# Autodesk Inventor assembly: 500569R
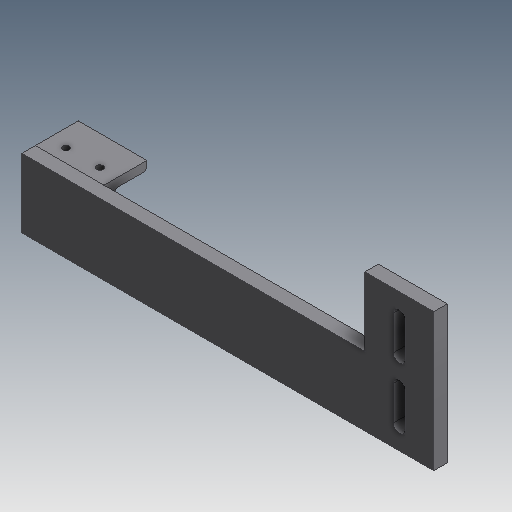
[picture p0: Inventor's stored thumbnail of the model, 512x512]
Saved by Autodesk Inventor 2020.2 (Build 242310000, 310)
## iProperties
Created: 2000-02
Part Number: 500569R
Description: WMT-AF,FH,CP,PLATE,MNT,PLOW
Document SubType Name: Assembly
Designer: sspink
Mass: 1566.77 g
Surface Area: 541.09 cm^2
Volume: 200.099 cm^3
Density: 7.83 g/cm^3
Control State: 0
Checked Out: False
Master: False
Shininess: 0.0
Length Units: 11269
Angle Units: 11279
Time Units: 11290
Mass Units: 11283
Length Display Precision: 3
Angle Display Precision: 2
Compacted: True
Cutlength: xx
Material Desc: xx
Material_number: xx
Dimensions: 102x41,8x305 mm
Mass: 1,567 kg
Density: 0.0
Volumn: 0.0
Area: 0.0
PropertySet Name: Model Information
Author: sspink
Revision Number: -
Title: WMT-AF,FH,CP,PLATE,MNT,PLOW
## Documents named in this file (3)
- D:\07 - DEMODATEN\OTX 2019 - Dataset - UPDATE - Dez2019\Designs\07-Packing machine\500569R.iam
- D:\07 - DEMODATEN\OTX 2019 - Dataset - UPDATE - Dez2019\Designs\07-Packing machine\Parts\ADSK-011498.ipt
- D:\07 - DEMODATEN\OTX 2019 - Dataset - UPDATE - Dez2019\Designs\07-Packing machine\Parts\ADSK-011499.ipt
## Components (2 placed, 2 different names)
1. ADSK-011498:1 — Mate:1, Flush:1, Flush:2
2. ADSK-011499:1 — Mate:1, Flush:1, Flush:2
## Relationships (3: Flush 2, Mate 1)
- Mate:1: ADSK-011498:1 ↔ ADSK-011499:1
- Flush:1: ADSK-011498:1 ↔ ADSK-011499:1
- Flush:2: ADSK-011498:1 ↔ ADSK-011499:1
